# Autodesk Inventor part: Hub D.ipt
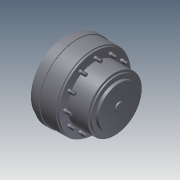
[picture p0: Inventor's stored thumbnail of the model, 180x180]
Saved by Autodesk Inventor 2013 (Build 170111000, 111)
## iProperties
Created: 2005-03
Part Number: Hub D.ipt
Material: Steel, Mild
Document SubType Name: Modeling
Designer: salex
Manufacturer: Standard
Standards Organization: Custom
Density: 7.86 g/cm^3
Mass: 456764 g
Surface Area: 9789.41 cm^2
Volume: 58112.5 cm^3
Author: salex
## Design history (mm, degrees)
revolve "Вращение1" stored, may be unused: angle "d20" = 90 deg
sketch "Эскиз2"
  geometry: C1 r 185 at (0, 0) reference; C2 r 11 at (-207.5, 0)
  constraints: 1 centre point
  dimensions: "d21" = 22 diameter of C2; "d22" = 0 vertical distance of C1.centre C2.centre; "d23" = 207.5 distance of C1.centre C2.centre
extrude "Выдавливание1" join sketch "Эскиз2" distance "d24" = 45; taper "d25" = 0 deg
thread "Thread1" dims "d29" = 30, "d30" = 0
pattern_circular "Круговой массив1" dims angle "d28" = 360 deg
body "Solid1"
sketch "Эскиз1"
  geometry: L1 (0, 0)-(417, 0); L2 (0, 0)-(0, 120.442); L3 (0, 120.442)-(45, 132.5); L4 (45, 132.5)-(45, 240); L5 (45, 240)-(80, 240); L6 (80, 240)-(80, 257.5); L7 (80, 257.5)-(120, 257.5); L8 (120, 257.5)-(120, 252.5); L9 (120, 252.5)-(230, 252.5); L10 (230, 252.5)-(230, 245); L11 (230, 245)-(242, 245); L12 (242, 245)-(242, 185); L13 (242, 185)-(377, 185); L14 (377, 185)-(377, 170); L15 (377, 170)-(387, 170); L16 (387, 170)-(387, 140); L17 (387, 140)-(407, 140); L18 (407, 140)-(407, 30); L19 (407, 30)-(417, 30); L20 (417, 30)-(417, 0)
  constraints: 40 end point, 14 parallel, 4 perpendicular, 1 horizontal, 1 other
  dimensions: "d0" = 60 diameter of L19 L1; "d1" = 10 distance of L18.end L19.end; "d2" = 280 diameter of L17 L1; "d3" = 20 distance of L16.end L17.end; "d4" = 340 diameter of L15 L1; "d5" = 10 distance of L14.end L15.end; "d6" = 135 distance of L12.end L13.end; "d7" = 370 diameter of L13 L1; "d9" = 490 diameter of L11 L1; "d10" = 12 distance of L10.end L11.end; "d11" = 515 diameter of L7 L1; "d12" = 505 diameter of L9 L1; "d13" = 242 distance between parallel lines of L12 L2; "d14" = 40 distance of L6.end L7.end; "d15" = 80 distance between parallel lines of L6 L2; "d16" = 35 distance of L4.end L5.end; "d17" = 105 deg angle of L2 L3; "d18" = 480 diameter of L5 L1; "d19" = 265 diameter of L3.end L1
